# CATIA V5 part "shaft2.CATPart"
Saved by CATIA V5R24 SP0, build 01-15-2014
Part number: shaft2
Bounding box of the stored display mesh (mm): x -14.905 to 14.905, y -14.825 to 22, z -100 to 100
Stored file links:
  G:\내 드라이브\04_WORK\00_LECTURE\CAD2020\exam\shaft2.CATPart
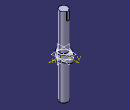
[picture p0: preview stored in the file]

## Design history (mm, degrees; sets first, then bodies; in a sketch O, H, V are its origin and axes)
Body1 (main body)
  Sketch1 on xy-plane, origin (0, 0, 0), H (1, 0, 0), V (0, 1, 0)
    circle A1 centre (0, 0) radius 10
    radius A1 = 10
  Pad1: profile Sketch1, direction (0, 0, 1), length 100, mirrored extent
  Sketch2 on end face of Pad1, origin (0, 0, 100), H (1, 0, 0), V (0, 1, 0)
    point P1 (0, 6)
    line L1 (2.5, 12) -> (2.5, 0)
    line L2 (2.5, 0) -> (-2.5, 0)
    line L3 (-2.5, 0) -> (-2.5, 12)
    line L4 (-2.5, 12) -> (2.5, 12)
    point P3 (2.5, 0)
    distance L1 L3 = 5
    distance L4 H = 12
    coincidence: P1 V, P3 H
    vertical: L1 V, L3 V
    horizontal: L2 H, L4 H
    equidistance: L1 L3 P1, L2 L4 P1
  Pad2: profile Sketch2, direction (0, 0, -1), length 20
  Sketch3 on xy-plane, origin (0, 0, 0), H (1, 0, 0), V (0, 1, 0)
    arc A1 centre (0, 0) radius 15 from (-13.7064, 6.0937) to (13.7064, 6.0938) ccw
    arc A2 centre (0, 16) radius 6 from (4.3611, 20.1207) to (-4.3611, 20.1207) ccw
    point P1 (0, 16)
    arc A3 centre (31.9817, -14.2187) radius 50 from (-4.3611, 20.1207) to (-13.7064, 6.0937) ccw
    arc A4 centre (-31.9817, -14.2188) radius 50 from (4.3611, 20.1207) to (13.7064, 6.0937) cw
    radius A1 = 15
    distance P1 V = 0
    distance P1 H = 16
    radius A2 = 6
    radius A3 = 50
    radius A4 = 50
    tangency: A3 A1, A3 A2, A4 A2, A4 A1
  Pad3: profile Sketch3, direction (0, 0, 1), length 8, mirrored extent
  Sketch4 on xy-plane, origin (0, 0, 0), H (1, 0, 0), V (0, 1, 0)
    projected arc E1 centre (-31.9817, -14.2188) radius 50 from (13.7064, 6.0937) to (4.3611, 20.1207) ccw from edge [face of Pad3 from Sketch3.A4 | end face of Pad3]
    projected arc E2 centre (0, 0) radius 15 from (-13.7064, 6.0937) to (13.7064, 6.0938) ccw from edge [face of Pad3 from Sketch3.A1 | end face of Pad3]
    projected arc E3 centre (0, 16) radius 6 from (4.3611, 20.1207) to (-4.3611, 20.1207) ccw from edge [face of Pad3 from Sketch3.A2 | end face of Pad3]
    projected arc E4 centre (31.9817, -14.2187) radius 50 from (-4.3611, 20.1207) to (-13.7064, 6.0937) ccw from edge [face of Pad3 from Sketch3.A3 | end face of Pad3]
